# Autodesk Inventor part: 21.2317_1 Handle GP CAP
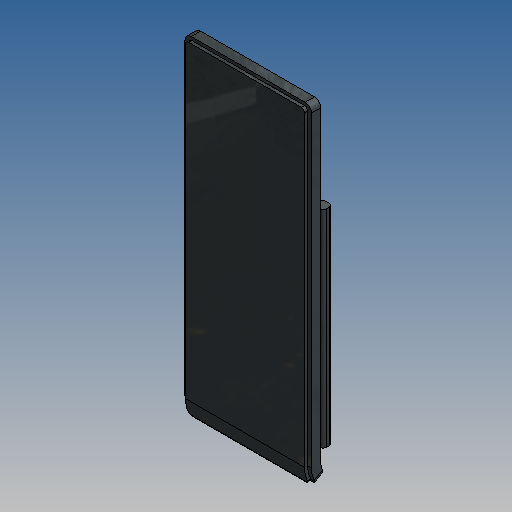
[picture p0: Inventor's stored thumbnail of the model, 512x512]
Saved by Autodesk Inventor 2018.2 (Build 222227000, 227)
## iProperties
Created: 2014-10
Part Number: 21.2317_1 Handle GP CAP
Material: ABS Plastik
Document SubType Name: Modeling
Designer: amoles
Density: 1.06 g/cm^3
Appearance: Default
Mass: 2.3608 g
Surface Area: 26.3401 cm^2
Volume: 2.22717 cm^3
Author: amoles
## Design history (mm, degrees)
feature "7A3"
body "Solid1"
